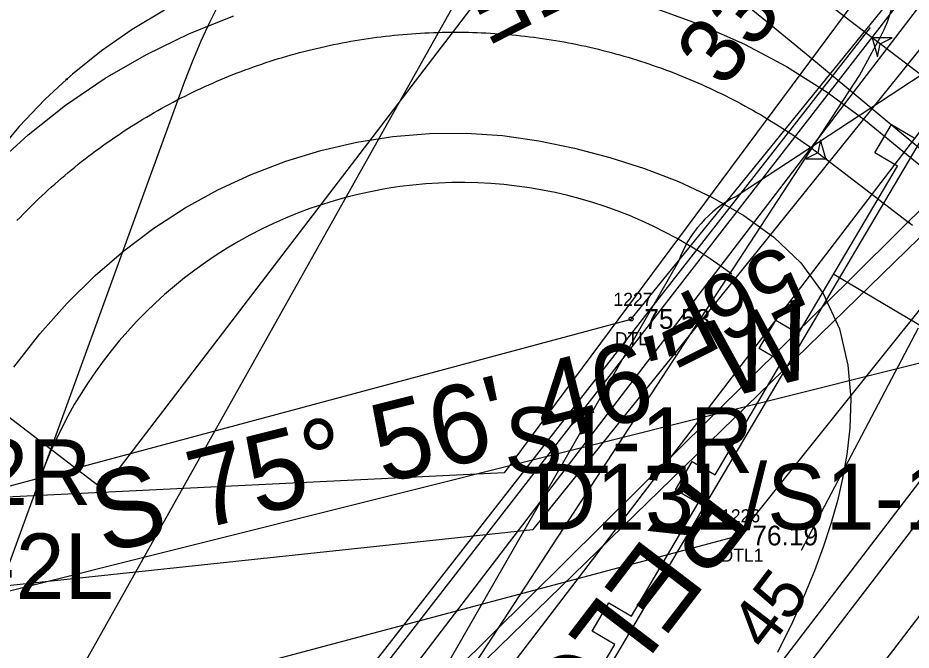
# Model space of a CAD drawing. Extents: x 2500794 to 2511032, y 910653 to 917533.
# Drawn here: x 2506136.2 to 2506204.2, y 914037.6 to 914085.8 of the extents above; entities that cross this region are included whole.
import ezdxf

# ---------------------------------------------------------------- set-up
doc = ezdxf.new("R2010")
doc.units = 0
for name, color, linetype in [('Default', 7, 'Continuous'), ('RD_EX_H2O', 7, 'Continuous'), ('RD_EX_H2O_txCode', 7, 'Continuous'), ('RD_EX_Road', 7, 'Continuous'), ('RD_EX_RW', 7, 'Continuous'), ('RD_EX_TX_H2O_ELEV', 7, 'Continuous'), ('RD_EX_VEG', 7, 'Continuous'), ('RD_HC_Cl', 7, 'Continuous'), ('RD_HC_Data', 7, 'Continuous'), ('RD_HC_Data_Rel', 7, 'Continuous'), ('RD_PD_ALT1_TnTmp', 7, 'Continuous'), ('RD_PD_ALT1_TrvlWay', 7, 'Continuous'), ('RD_PD_ALT2_TrvlWay', 7, 'Continuous'), ('RD_PD_CstnLmt', 7, 'Continuous'), ('RD_PD_Detour', 7, 'Continuous'), ('RD_PD_GR', 7, 'Continuous'), ('RD_PD_PaintMed', 7, 'Continuous'), ('RD_PD_RW', 7, 'Continuous'), ('RD_PD_Signals', 7, 'Continuous'), ('RD_SMD_Locator', 7, 'Continuous')]:
    doc.layers.add(name, color=color, linetype=linetype)

# ---------------------------------------------------------------- blocks, each defined once
blk = doc.blocks.new('POINT_DISPLAY')
at = {"layer": 'Default'}
blk.add_line((0, 0), (0, 0), dxfattribs=at)
blk = doc.blocks.new('Non-Aquatic Resource (Roadside Ditch)')
at = {"layer": 'Default'}
for points in [[(636599.652, 232207.16), (636598.419, 232206.49), (636582.656, 232188.724), (636568.007, 232168.982)], [(636600.779, 232205.668), (636583.794, 232186.809), (636568.556, 232167.887)]]:
    blk.add_lwpolyline(points, dxfattribs=at)
blk = doc.blocks.new('Non-Wetland Waters (Tributaries)')
at = {"layer": 'Default'}
for points in [[(636568.007, 232168.982), (636555.213, 232168.36), (636533.617, 232161.173), (636520.376, 232160.723), (636495.066, 232165.975), (636473.824, 232164.283), (636451.693, 232146.366)], [(636463.424, 232143.109), (636471.33, 232152.976), (636485.289, 232157.041), (636505.816, 232154.48), (636536.861, 232159.182), (636555.919, 232166.539), (636568.556, 232167.887)]]:
    blk.add_lwpolyline(points, dxfattribs=at)

msp = doc.modelspace()

# ---------------------------------------------------------------- linework, layer by layer
at = {"layer": 'RD_EX_H2O_txCode'}
for points in [[(2506115.848, 914044.827), (2506182.908, 914062.824), (2506228.814, 914119.393), (2506295.706, 914196.353), (2506352.358, 914270.515), (2506416.017, 914356.388), (2506433.302, 914386.441), (2506438.239, 914390.613)], [(2506111.845, 914025.213), (2506191.122, 914046.339), (2506240.906, 914108.602), (2506304.096, 914190.052), (2506361.191, 914264.825), (2506427.45, 914348.312), (2506450.333, 914379.52)]]:
    msp.add_lwpolyline(points, dxfattribs=at)
at = {"layer": 'RD_EX_Road'}
msp.add_lwpolyline([(2506114.007, 913933.801), (2506123.607, 913945.349), (2506183.697, 914019.9), (2506246.754, 914102.24), (2506309.518, 914184.625), (2506366.784, 914260.378), (2506431.546, 914345.252), (2506455.95, 914376.736), (2506469.753, 914395.23), (2506492.702, 914425.08), (2506555.841, 914508.256), (2506617.748, 914589.016), (2506679.77, 914670.808), (2506740.348, 914750.219)], dxfattribs=at)
at = {"layer": 'RD_EX_RW'}
msp.add_line((2506145.95, 914009.619), (2506722.671, 914763.958), dxfattribs=at)
at = {"layer": 'RD_EX_VEG'}
msp.add_line((2506140.026, 914005.323), (2506726.018, 914761.038), dxfattribs=at)
at = {"layer": 'RD_HC_Cl'}
msp.add_line((2506230.498, 914065.873), (2506112.069, 914036.227), dxfattribs=at)
at = {"layer": 'RD_HC_Data_Rel'}
msp.add_line((2506234.439, 914115.768), (2506136.125, 913987.174), dxfattribs=at)
at = {"layer": 'RD_PD_ALT1_TnTmp'}
for p, q in [((2506201.262, 914084.237), (2506197.165, 914087.373)), ((2506209.245, 914078.124), (2506201.262, 914084.237)), ((2506197.713, 914075.029), (2506197.713, 914075.029)), ((2506197.713, 914075.029), (2506204.051, 914070.184)), ((2506206.922, 914042.959), (2506137.76, 913952.5))]:
    msp.add_line(p, q, dxfattribs=at)
for points in [[(2506205.26, 914075.477), (2506202.232, 914077.988), (2506199.336, 914080.414), (2506196.509, 914082.769), (2506193.679, 914085.099), (2506190.944, 914087.321)], [(2506147.385, 914086.335), (2506144.939, 914084.865), (2506142.599, 914083.238), (2506140.378, 914081.456), (2506139.949, 914081.081)], [(2506184.794, 914086.457), (2506188.214, 914085.227), (2506191.536, 914083.753), (2506194.743, 914082.042), (2506197.817, 914080.103), (2506200.743, 914077.947), (2506203.598, 914075.593), (2506206.444, 914073.261)], [(2506126.221, 914060.812), (2506126.915, 914062.717), (2506128.2, 914065.833), (2506129.839, 914068.865), (2506131.882, 914071.747), (2506134.338, 914074.403), (2506137.016, 914076.857), (2506139.865, 914079.112), (2506142.87, 914081.154), (2506146.016, 914082.973), (2506149.285, 914084.56), (2506152.66, 914085.906)], [(2506136.165, 914070.322), (2506136.395, 914070.563), (2506136.627, 914070.802), (2506136.861, 914071.04), (2506137.096, 914071.276), (2506137.333, 914071.51), (2506137.572, 914071.742), (2506137.812, 914071.973), (2506138.055, 914072.202), (2506138.299, 914072.429), (2506138.544, 914072.655), (2506138.791, 914072.879), (2506139.04, 914073.101), (2506139.29, 914073.321), (2506139.542, 914073.539), (2506139.796, 914073.755), (2506140.051, 914073.97), (2506140.307, 914074.183), (2506140.565, 914074.394), (2506140.825, 914074.603), (2506141.086, 914074.81), (2506141.349, 914075.015), (2506141.613, 914075.218), (2506141.879, 914075.42), (2506142.146, 914075.619), (2506142.414, 914075.817), (2506142.684, 914076.013), (2506142.955, 914076.206), (2506143.228, 914076.398), (2506143.502, 914076.587), (2506143.778, 914076.775), (2506144.054, 914076.961), (2506144.333, 914077.145), (2506144.612, 914077.326), (2506144.893, 914077.506), (2506145.175, 914077.683), (2506145.458, 914077.859), (2506145.743, 914078.032), (2506146.029, 914078.204), (2506146.316, 914078.373), (2506146.604, 914078.54), (2506146.894, 914078.706), (2506147.185, 914078.869), (2506147.477, 914079.03), (2506147.77, 914079.188), (2506148.064, 914079.345), (2506148.359, 914079.5), (2506148.656, 914079.652), (2506148.953, 914079.802), (2506149.252, 914079.95), (2506149.551, 914080.096), (2506149.852, 914080.24), (2506150.154, 914080.382), (2506150.457, 914080.521), (2506150.761, 914080.658), (2506151.065, 914080.793), (2506151.371, 914080.926), (2506151.678, 914081.056), (2506151.985, 914081.185), (2506152.294, 914081.311), (2506152.603, 914081.435), (2506152.914, 914081.556), (2506153.225, 914081.676), (2506153.537, 914081.793), (2506153.85, 914081.908), (2506154.164, 914082.02), (2506154.478, 914082.131), (2506154.794, 914082.239), (2506155.11, 914082.344), (2506155.427, 914082.448), (2506155.744, 914082.549), (2506156.063, 914082.648), (2506156.382, 914082.744), (2506156.701, 914082.838), (2506157.022, 914082.93), (2506157.343, 914083.02), (2506157.665, 914083.107), (2506157.987, 914083.192), (2506158.31, 914083.274), (2506158.634, 914083.355), (2506158.958, 914083.432), (2506159.282, 914083.508), (2506159.608, 914083.581), (2506159.933, 914083.652), (2506160.259, 914083.72), (2506160.586, 914083.786), (2506160.913, 914083.85), (2506161.241, 914083.911), (2506161.569, 914083.97), (2506161.898, 914084.027), (2506162.227, 914084.081), (2506162.556, 914084.133), (2506162.885, 914084.182), (2506163.215, 914084.229), (2506163.546, 914084.274), (2506163.876, 914084.316), (2506164.207, 914084.356), (2506164.539, 914084.394), (2506164.87, 914084.429), (2506165.202, 914084.461), (2506165.534, 914084.491), (2506165.866, 914084.519), (2506166.198, 914084.545), (2506166.531, 914084.568), (2506166.864, 914084.588), (2506167.196, 914084.607), (2506167.529, 914084.622), (2506167.862, 914084.636), (2506168.196, 914084.647), (2506168.529, 914084.655), (2506168.862, 914084.661), (2506169.195, 914084.665), (2506169.529, 914084.666), (2506169.862, 914084.665), (2506170.195, 914084.662), (2506170.529, 914084.656), (2506170.862, 914084.647), (2506171.195, 914084.637), (2506171.528, 914084.623), (2506171.861, 914084.608), (2506172.194, 914084.59), (2506172.527, 914084.569), (2506172.859, 914084.546), (2506173.191, 914084.521), (2506173.524, 914084.493), (2506173.856, 914084.463), (2506174.187, 914084.431), (2506174.519, 914084.396), (2506174.85, 914084.359), (2506175.181, 914084.319), (2506175.512, 914084.277), (2506175.842, 914084.233), (2506176.172, 914084.186), (2506176.502, 914084.136), (2506176.831, 914084.085), (2506177.16, 914084.031), (2506177.489, 914083.974), (2506177.817, 914083.916), (2506178.144, 914083.854), (2506178.472, 914083.791), (2506178.798, 914083.725), (2506179.125, 914083.657), (2506179.45, 914083.586), (2506179.776, 914083.513), (2506180.1, 914083.438), (2506180.424, 914083.36), (2506180.748, 914083.28), (2506181.071, 914083.198), (2506181.393, 914083.113), (2506181.715, 914083.026), (2506182.036, 914082.936), (2506182.357, 914082.845), (2506182.677, 914082.751), (2506182.996, 914082.654), (2506183.314, 914082.556), (2506183.632, 914082.455), (2506183.949, 914082.351), (2506184.265, 914082.246), (2506184.58, 914082.138), (2506184.895, 914082.028), (2506185.209, 914081.916), (2506185.522, 914081.801), (2506185.834, 914081.684), (2506186.145, 914081.565), (2506186.456, 914081.443), (2506186.765, 914081.32), (2506187.074, 914081.194), (2506187.381, 914081.065), (2506187.688, 914080.935), (2506187.994, 914080.802), (2506188.299, 914080.668), (2506188.603, 914080.531), (2506188.906, 914080.391), (2506189.207, 914080.25), (2506189.508, 914080.106), (2506189.808, 914079.961), (2506190.107, 914079.813), (2506190.404, 914079.663), (2506190.701, 914079.51), (2506190.996, 914079.356), (2506191.291, 914079.199), (2506191.584, 914079.041), (2506191.876, 914078.88), (2506192.166, 914078.717), (2506192.456, 914078.552), (2506192.745, 914078.385), (2506193.032, 914078.216), (2506193.318, 914078.044), (2506193.602, 914077.871), (2506193.886, 914077.696), (2506194.168, 914077.518), (2506194.449, 914077.339), (2506194.729, 914077.157), (2506195.007, 914076.974), (2506195.284, 914076.788), (2506195.559, 914076.601), (2506195.833, 914076.411), (2506196.106, 914076.22), (2506196.378, 914076.026), (2506196.648, 914075.831), (2506196.916, 914075.633), (2506197.183, 914075.434), (2506197.449, 914075.233), (2506197.713, 914075.029)], [(2506139.949, 914081.081), (2506138.285, 914079.528), (2506136.32, 914077.471), (2506134.479, 914075.305)], [(2506135.929, 914059.149), (2506137.91, 914061.708), (2506139.981, 914064.041), (2506142.12, 914066.147), (2506144.305, 914068.026), (2506146.586, 914069.734), (2506148.966, 914071.277), (2506151.442, 914072.649), (2506153.995, 914073.839), (2506156.616, 914074.845), (2506159.296, 914075.661), (2506162.022, 914076.285), (2506164.781, 914076.712), (2506167.56, 914076.941), (2506170.344, 914076.967), (2506173.121, 914076.785), (2506175.874, 914076.398), (2506178.596, 914075.836), (2506181.279, 914075.128), (2506183.924, 914074.278), (2506186.509, 914073.284), (2506189.042, 914072.113), (2506191.489, 914070.714), (2506193.779, 914069.046), (2506195.819, 914067.09), (2506197.534, 914064.761), (2506198.754, 914062.071), (2506199.408, 914059.305), (2506199.617, 914056.775), (2506199.553, 914054.509), (2506199.329, 914052.506), (2506199.006, 914050.691), (2506198.608, 914048.981), (2506198.116, 914047.235), (2506197.534, 914045.46), (2506196.865, 914043.653), (2506196.108, 914041.812), (2506195.176, 914039.741), (2506194.051, 914037.443)], [(2506204.051, 914070.184), (2506204.314, 914069.978)]]:
    msp.add_lwpolyline(points, dxfattribs=at)
for points in [[(2506201.262, 914084.237), (2506201.651, 914082.788), (2506201.857, 914083.781), (2506202.762, 914084.238)], [(2506197.713, 914075.029), (2506197.323, 914076.478), (2506197.118, 914075.485), (2506196.213, 914075.027)]]:
    msp.add_lwpolyline(points, close=True, dxfattribs=at)
for centre in [(2506201.262, 914084.237), (2506201.262, 914084.237), (2506139.949, 914081.081), (2506139.949, 914081.081), (2506197.713, 914075.029), (2506197.713, 914075.029), (2506197.713, 914075.029), (2506197.713, 914075.029), (2506204.051, 914070.184), (2506204.051, 914070.184)]:
    msp.add_circle(centre, 0.0417, dxfattribs=at)
msp.add_arc((2506169.922, 914039.216), 34, 52.60071, 159.98651, dxfattribs=at)
at = {"layer": 'RD_PD_ALT1_TrvlWay'}
msp.add_line((2506145.473, 913972.774), (2506215.723, 914064.66), dxfattribs=at)
at = {"layer": 'RD_PD_ALT2_TrvlWay'}
msp.add_line((2506148.92, 914080.9), (2506117.261, 913993.982), dxfattribs=at)
for centre, radius, start, end in [((2506194.961, 914064.13), 49, 99.29832, 159.98651), ((2506191.891, 914082.881), 30, 322.60071, 99.29832)]:
    msp.add_arc(centre, radius, start, end, dxfattribs=at)
at = {"layer": 'RD_PD_CstnLmt'}
msp.add_line((2506137.493, 914003.497), (2506201.117, 914085.014), dxfattribs=at)
at = {"layer": 'RD_PD_Detour'}
for p, q in [((2506211.359, 914085.58), (2506190.903, 914072.164)), ((2506186.504, 914067.21), (2506160.76, 914022.308))]:
    msp.add_line(p, q, dxfattribs=at)
msp.add_arc((2506194.961, 914064.13), 9, 116.7959, 159.98651, dxfattribs=at)
at = {"layer": 'RD_PD_GR'}
for p, q in [((2506206.65, 914079.342), (2506175.845, 914027.251)), ((2506201.46, 914075.477), (2506202.732, 914077.629)), ((2506202.732, 914077.629), (2506204.461, 914076.607)), ((2506203.188, 914074.455), (2506201.46, 914075.477)), ((2506195.655, 914061.716), (2506203.188, 914074.455)), ((2506192.654, 914060.587), (2506193.927, 914062.738)), ((2506193.927, 914062.738), (2506195.655, 914061.716)), ((2506194.382, 914059.564), (2506192.654, 914060.587)), ((2506189.292, 914050.957), (2506194.382, 914059.564)), ((2506186.291, 914049.827), (2506187.564, 914051.979)), ((2506187.564, 914051.979), (2506189.292, 914050.957)), ((2506188.02, 914048.805), (2506186.291, 914049.827)), ((2506182.93, 914040.197), (2506188.02, 914048.805)), ((2506179.929, 914039.067), (2506181.201, 914041.219)), ((2506181.201, 914041.219), (2506182.93, 914040.197)), ((2506181.657, 914038.045), (2506179.929, 914039.067)), ((2506176.567, 914029.438), (2506181.657, 914038.045))]:
    msp.add_line(p, q, dxfattribs=at)
for centre, start, end in [((2506227.153, 914052.577), 149.64841, 149.64855), ((2506223.626, 914035.48), 142.60057, 142.60071)]:
    msp.add_arc(centre, 30, start, end, dxfattribs=at)
at = {"layer": 'RD_PD_PaintMed'}
for p, q in [((2506279.06, 914144.645), (2506146.33, 914013.08)), ((2506137.493, 914003.497), (2506268.772, 914131.14)), ((2506198.327, 914066.235), (2506206.447, 914061.434)), ((2506195.867, 914045.225), (2506204.766, 914062.163))]:
    msp.add_line(p, q, dxfattribs=at)
at = {"layer": 'RD_PD_RW'}
for q in [(2506397.815, 914383.508), (2506130.805, 914058.961)]:
    msp.add_line((2506142.721, 914049.851), q, dxfattribs=at)
at = {"layer": 'RD_PD_Signals'}
for p, q in [((2506176.833, 914100.024), (2506137.936, 914030.621)), ((2506200.298, 914081.358), (2506201.891, 914084.307)), ((2506145.437, 913997.424), (2506200.298, 914081.358))]:
    msp.add_line(p, q, dxfattribs=at)
msp.add_arc((2506193.094, 914089.062), 10, 331.61386, 86.67362, dxfattribs=at)
at = {"layer": 'RD_SMD_Locator'}
for centre in [(2506182.908, 914062.824), (2506191.122, 914046.339)]:
    msp.add_circle(centre, 0.15, dxfattribs=at)

# ---------------------------------------------------------------- block references
at = {"layer": 'Default', "xscale": 3.937007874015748, "yscale": 3.937007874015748}
for name, p in [('Non-Aquatic Resource (Roadside Ditch)', (0, 0)), ('Non-Aquatic Resource (Roadside Ditch)', (0, 0)), ('Non-Wetland Waters (Tributaries)', (0, 0)), ('POINT_DISPLAY', (2506173.257, 914051.111)), ('POINT_DISPLAY', (2506173.257, 914051.111)), ('POINT_DISPLAY', (2506175.418, 914046.798)), ('POINT_DISPLAY', (2506175.418, 914046.798))]:
    msp.add_blockref(name, p, dxfattribs=at)
at = {"layer": 'RD_EX_H2O', "xscale": 3.937007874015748, "yscale": 3.937007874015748}
msp.add_blockref('Non-Wetland Waters (Tributaries)', (0, 0), dxfattribs=at)

# ---------------------------------------------------------------- texts
at = {"layer": 'Default'}
for s, p in [('S1-1R', (2506173.257, 914051.111)), ('S1-1R', (2506173.257, 914051.111)), ('S1-2R', (2506122.887, 914048.662)), ('S1-2R', (2506122.887, 914048.662)), ('D13L/S1-1L', (2506175.418, 914046.798)), ('D13L/S1-1L', (2506175.418, 914046.798)), ('S1-2L', (2506125.664, 914041.494)), ('S1-2L', (2506125.664, 914041.494))]:
    msp.add_text(s, height=5, dxfattribs=at).set_placement(p)
at = {"layer": 'RD_EX_H2O_txCode'}
for s, p in [('1227', (2506181.561, 914063.824)), ('DTL', (2506181.664, 914060.824)), ('1226', (2506189.752, 914047.339)), ('DTL1', (2506189.712, 914044.339))]:
    msp.add_text(s, height=1, dxfattribs=at).set_placement(p)
at = {"layer": 'RD_EX_TX_H2O_ELEV'}
for s, p in [('75.58', (2506183.908, 914062.074)), ('76.19', (2506192.122, 914045.589))]:
    msp.add_text(s, height=1.5, dxfattribs=at).set_placement(p)
at = {"layer": 'RD_HC_Data'}
msp.add_text('S 75%%d 56\' 46" W', height=6, rotation=14.05393, dxfattribs=at).set_placement((2506142.74, 914044.936))
at = {"layer": 'RD_HC_Data_Rel'}
msp.add_text('RELOC. PC=10+27.17', height=6, rotation=232.60071, dxfattribs=at).set_placement((2506187.439, 914050.999))
at = {"layer": 'RD_PD_Detour'}
msp.add_text('56F', height=5, rotation=206.79591, dxfattribs=at).set_placement((2506194.387, 914068.647))
at = {"layer": 'RD_PD_PaintMed'}
msp.add_text('45', height=3.75, rotation=52.60071, dxfattribs=at).set_placement((2506193.192, 914037.411))
at = {"layer": 'RD_PD_Signals'}
for s, rotation, p in [('25F', 206.79591, (2506180.214, 914093.329)), ('33F', 52.60071, (2506189.983, 914080.284))]:
    msp.add_text(s, height=5, rotation=rotation, dxfattribs=at).set_placement(p)

doc.saveas('drawing.dxf')
